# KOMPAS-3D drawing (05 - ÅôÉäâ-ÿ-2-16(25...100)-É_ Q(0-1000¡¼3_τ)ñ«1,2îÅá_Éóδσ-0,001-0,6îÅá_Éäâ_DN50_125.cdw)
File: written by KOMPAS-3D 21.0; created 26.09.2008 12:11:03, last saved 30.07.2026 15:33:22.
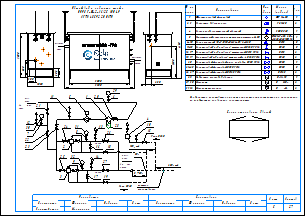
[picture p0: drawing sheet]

Sheets 1-2: A3, landscape

Document properties: Наименование: Макро:21; Автор: RaskoAdmin; Форматы листов документа: 2xA3; Полное имя файла: \\ur38nt01\Departments\КТО\КБ ПУРДГ\Заявки\Прайс-лист на типовые шкафы ГРПШ\ПУРДГ_стандарт_30_04_2026\ПУРДГ с РДГ(Н, В)\ПУРДГ-Ш-2-16(25...100)-Р_ Q(0-1000нм3_ч)до1,2МПа_Рвых-0,001-0,6МПа_РДГ_DN50_125.cdw

Title block, sheet 1: Наименование: Пункт учета газа / ПУГ-Ш-400-Р / ЛГТИ.485922.001ТУ; designation: ЛГТИ.03.4411141; sheet number: 1; Количество листов документа: 2; organisation: ООО "ЭЛЬСТЕР Газэлектроника"; Форматы листов документа: A3; stored path: C:\Рабочие документы\Компас\ПУГ\Схема.cdw; Разработал: Устинов; Проверил: Кошкин; Утвердил: Кошкин
Title block, sheet 2: sheet number: 2; stored path: D:\Рабочие документы\Заявки\ПУРДГ\ПУРДГ-ШУЭО-2-100-Р 4411220.cdw; designation, second copy: ЛГТИ.03.4411141-

Views: Вид 1, Вид 2
Referenced files: wcvoit.frw
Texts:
  Normal
  № на
  схеме
  Усл.
  обозн.
  Марка
  (модель)
  Кол.
  Фильтр газовый фланцевый
  ФГ 16-50
  Регулятор давления газа
  РДГ-50
  Клапан предохранительный сбросной
  КПС DN20
  Измерительный комплекс с ротационным счетчиком Ду50
  СГ-ЭК-Р-(0,2...2,0)-
  Кран кнопочный VE-РАСКО-НЗ-1,6-G1/2-М20
  DN15
  Кран шаровой "под приварку" штуцерный DN20 PN16
  DN20
  Кран шаровой "под приварку" штуцерный DN15 PN16
  Кран шаровой "под приварку" штуцерный п/п DN20 PN16
  Кран шаровой фланцевый с мех. приводом DN50 PN16
  Кран шаровой фланцевый DN50 PN16
  Кран шаровой фланцевый DN125 PN16
  DN50
  DN125
  Индикатор перепада давления
  Манометр
  Манометр-напоромер
  Delta 15
  0...     МПа
  0...     кПа
  Общий вид и габариты шкафа
  ПУРДГ-Ш-2-16(25...100)-Р
  Выход газа
  Вход газа
  logo-rasko-ge.png
  DN 1
  местное
  сопротивление
  Римп DN20
  Выход
  газа
  Р=     кПа
  Вход
  Р=       МПа
  PDI
  Схема открывания дверей
  Предприятие изготовитель может заменять комплектующие на аналогичные,
  не ухудшающие заявленных характеристик.
  Должность
  Конструктор
  Фамилия
  Подпись
  Дата
  Согласовано
  Максимкин
  Лист
  Листов
  POLYLINE_STYLE_0.18_RGB_0_0_0
  POLYLINE_STYLE_0.50_RGB_0_0_0
  POLYLINE_STYLE_0.34_RGB_0_0_0
  PHANTOM_RGB_0_0_0_SC_1_THICK_0.18
  K5LT_THIN_RGB_0_0_0_THICK_0.18
  K5LT32769_RGB_0_0_0_THICK_0.18
  K5LT12_RGB_0_0_0_SC_1_THICK_0.18
  K5LT_DASHED_RGB_0_0_0_SC_1_THICK_0.18
  ACISOTGL_RGB_0_0_0_SC_0.8_THICK_0.25
  CONTINUOUS_RGB_0_127_31_THICK_0.3
  CONTINUOUS_RGB_0_0_255_THICK_0.35
  CONTINUOUS_RGB_255_0_0_THICK_0.35
  POLYLINE_STYLE_0.25_RGB_0_0_0
  CONTINUOUS_RGB_0_0_0_THICK_0.5
  POLYLINE_STYLE_0.35_RGB_0_0_255
  CONTINUOUS_RGB_0_0_0_THICK_0.4
  CONTINUOUS_RGB_0_0_0_THICK_0.35
  НЕВИДИМАЯ_RGB_0_0_0_SC_0.3_THICK_0.25
  СONTINUOUS_RGB_0_0_0_THICK_0.25
  ОСЕВАЯ2_RGB_248_153_30_SC_0.3_THICK_0.25
  Без оформления
Dimensions and other numbers on the sheet: 1; 2, 3; 2; 4; 5; 6-10; 11-15; 16, 17; 18, 19; 20; 21-25; 26, 27; 28; 29, 30; 31, 32; 1500; 250; 300; 1050; 550; 305; 3000; 4130; 2000; 3300; 5,,,7DN 1; 7; 30; 12; 21; 22; 23; 11; 6; 29; 24; 31; 8; 13; 26; 18; 10; 15; 25; 32; 9; 3; 14; 27; 19; 16; 17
